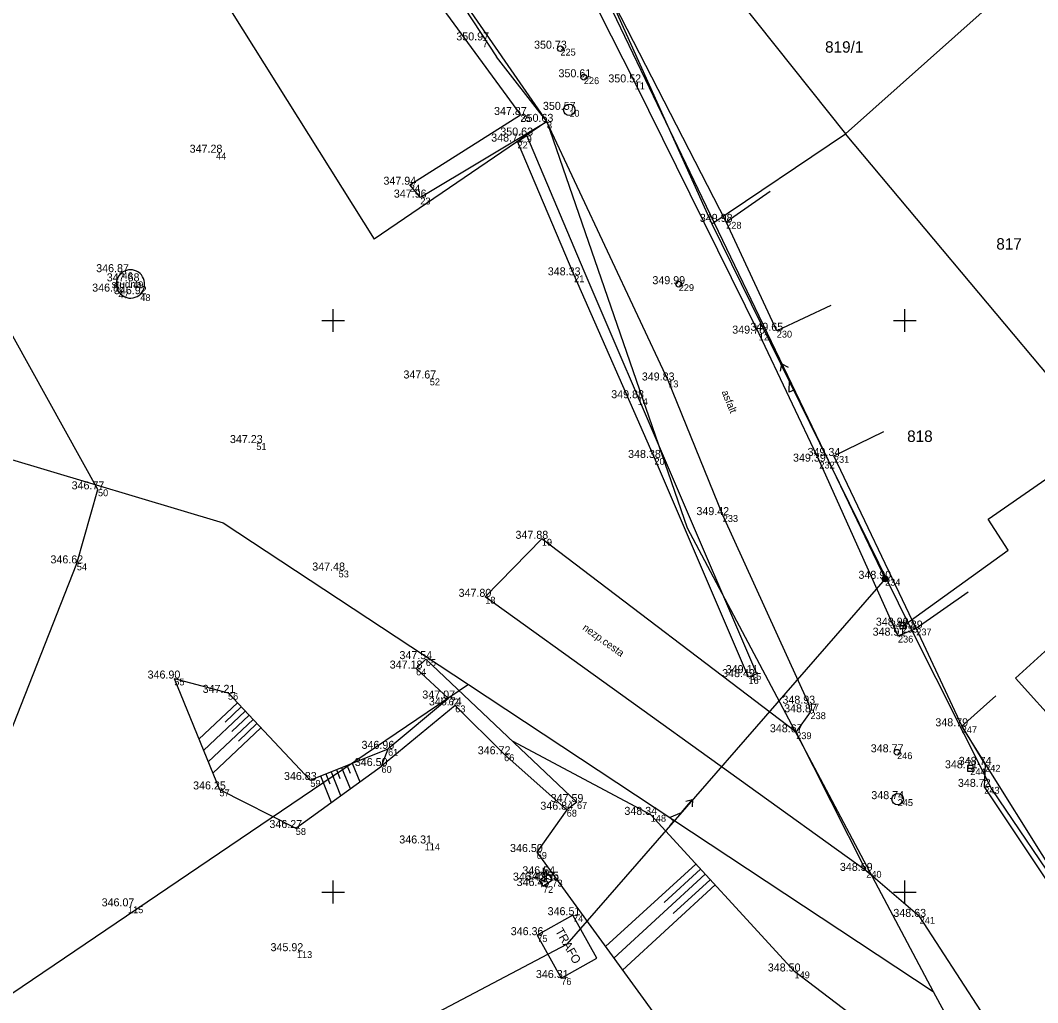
# Model space of a CAD drawing. Extents: x -614046 to -613877, y -1156755 to -1156623.
# Drawn here: x -613970.95 to -613935.35, y -1156683.87 to -1156649.5 of the extents above; entities that cross this region are included whole.
import ezdxf

# ---------------------------------------------------------------- set-up
doc = ezdxf.new("R2010")
doc.units = 0
for name, color, linetype in [('1-bod', 7, 'Continuous'), ('10-silnice', 7, 'Continuous'), ('11-zpevněné plochy', 7, 'Continuous'), ('12-nezpevněné plochy', 7, 'Continuous'), ('14-terénní hrany', 7, 'Continuous'), ('15-šrafy', 7, 'Continuous'), ('2-bod výška', 7, 'Continuous'), ('24-prisky', 7, 'Continuous'), ('25-sloupy', 7, 'Continuous'), ('27-kanalizace značky', 7, 'Continuous'), ('28-vodovod značky', 7, 'Continuous'), ('3-bod číslo', 7, 'Continuous'), ('32-elekrické vedení', 7, 'Continuous'), ('40-popisy povrchů', 7, 'Continuous'), ('41-Popis objektů', 7, 'Continuous'), ('50-hranice parcel KN', 7, 'Continuous'), ('61-hektarová síť', 7, 'Continuous'), ('7-plot', 7, 'Continuous')]:
    doc.layers.add(name, color=color, linetype=linetype)

# ---------------------------------------------------------------- blocks, each defined once
blk = doc.blocks.new('6.30')
at = {"layer": '27-kanalizace značky'}
blk.add_line((-0.249, 0.002), (0.251, 0.002), dxfattribs=at)
blk.add_lwpolyline([(-0.25, -0.248), (0.251, -0.249), (0.251, 0.251), (-0.249, 0.251)], close=True, dxfattribs=at)
blk = doc.blocks.new('6.14A_1')
at = {"layer": '28-vodovod značky'}
blk.add_circle((0, 0), 0.25, dxfattribs=at)
blk = doc.blocks.new('6.20_1')
at = {"layer": '27-kanalizace značky'}
blk.add_circle((0, 0), 0.5, dxfattribs=at)
blk = doc.blocks.new('6.01A_1')
at = {"layer": '25-sloupy'}
for radius in [0.25, 0.2, 0.15, 0.1, 0.05]:
    blk.add_circle((0, 0), radius, dxfattribs=at)
blk = doc.blocks.new('PE_1')
at = {"layer": '24-prisky'}
for p, q in [((-0.25, 1.126), (-0.25, 0.5)), ((-0.25, 0.5), (0, 0.875)), ((-0.11, 0.245), (0, 0)), ((0, 0.875), (0, 0)), ((0, 0), (0.11, 0.245))]:
    blk.add_line(p, q, dxfattribs=at)
blk = doc.blocks.new('6.60_1')
at = {"layer": '32-elekrické vedení'}
for points in [[(-3, 0), (-2.5, 0), (-2.5, 0.5), (-1.5, 0), (0, 0)], [(-0.5, 0.375), (0, 0), (-0.5, -0.375)]]:
    blk.add_lwpolyline(points, dxfattribs=at)
blk = doc.blocks.new('POINT_DISPLAY')
blk.add_line((0, 0), (0, 0))

msp = doc.modelspace()

# ---------------------------------------------------------------- linework, layer by layer
at = {"layer": '10-silnice'}
for points in [[(-613960.9, -1156628.99), (-613958.35, -1156634.24), (-613954.84, -1156641.03), (-613949.45, -1156651.67), (-613945.11, -1156660.46), (-613942.99, -1156664.94), (-613940.24, -1156671.03), (-613939.6, -1156670.78), (-613938.01, -1156674.2), (-613937.19, -1156675.55), (-613937.22, -1156676.32), (-613930.03, -1156687.11), (-613926.48, -1156692.5), (-613921.2, -1156700), (-613918.96, -1156702.74), (-613916.95, -1156704.04), (-613916.91, -1156705.25), (-613915.47, -1156707.93), (-613915.57, -1156709.01), (-613915.47, -1156709.37), (-613915.3, -1156709.66), (-613915.08, -1156709.85), (-613914.78, -1156710.02), (-613906.4, -1156710.82)], [(-613937.12, -1156718.51), (-613933.57, -1156717.58), (-613925.62, -1156715.79), (-613924.84, -1156714.33), (-613924.32, -1156712.22), (-613924.87, -1156710.22), (-613924.77, -1156707.77), (-613925.4, -1156704.88), (-613927.05, -1156701.37), (-613930.42, -1156695.41), (-613933.78, -1156689.64), (-613939.48, -1156680.87), (-613941.35, -1156679.26), (-613943.8, -1156674.41), (-613943.3, -1156673.71), (-613943.36, -1156673.41), (-613946.37, -1156666.81), (-613948.28, -1156662.1), (-613952.52, -1156653.05)]]:
    msp.add_lwpolyline(points, dxfattribs=at)
at = {"layer": '11-zpevněné plochy'}
for start, end in [(123.9608, 212.772), (212.772, 123.9608)]:
    msp.add_arc((-613967.093, -1156658.721), 0.496, start, end, dxfattribs=at)
at = {"layer": '12-nezpevněné plochy'}
for p, q in [((-613968.23, -1156665.91), (-613971.76, -1156659.56)), ((-613968.97, -1156668.5), (-613968.23, -1156665.91)), ((-613971.92, -1156675.99), (-613968.97, -1156668.5))]:
    msp.add_line(p, q, dxfattribs=at)
for points in [[(-613954.68, -1156669.67), (-613952.7, -1156667.64)], [(-613943.8, -1156674.41), (-613952.7, -1156667.64)], [(-613941.35, -1156679.26), (-613954.68, -1156669.67)]]:
    msp.add_lwpolyline(points, dxfattribs=at)
at = {"layer": '14-terénní hrany'}
for p, q in [((-613965.56, -1156672.53), (-613963.68, -1156673.03)), ((-613963.68, -1156673.03), (-613960.8, -1156676.08)), ((-613960.8, -1156676.08), (-613958.08, -1156674.99)), ((-613961.31, -1156677.76), (-613958.31, -1156675.59))]:
    msp.add_line(p, q, dxfattribs=at)
for points in [[(-613965.56, -1156672.53), (-613963.98, -1156676.41), (-613961.31, -1156677.76)], [(-613940.16, -1156716.75), (-613937.91, -1156714.4), (-613933.94, -1156711.13), (-613930, -1156706.58), (-613928.58, -1156705.01), (-613927.95, -1156702.75), (-613928.18, -1156700.53), (-613933.55, -1156692.05), (-613939.5, -1156686.1), (-613943.86, -1156682.78), (-613948.89, -1156677.3), (-613953.73, -1156674.72)], [(-613951.83, -1156677.12), (-613952.88, -1156678.6), (-613948.44, -1156684.71), (-613942.44, -1156689.03), (-613937.52, -1156693.96), (-613931.49, -1156703.13), (-613933.8, -1156705.42), (-613937.38, -1156709.49), (-613940.48, -1156713.13)]]:
    msp.add_lwpolyline(points, dxfattribs=at)
at = {"layer": '15-šrafy'}
for p, q in [((-613963.353, -1156673.377), (-613964.698, -1156674.647)), ((-613963.078, -1156673.668), (-613964.536, -1156675.045)), ((-613963.215, -1156673.522), (-613963.776, -1156674.052)), ((-613962.941, -1156673.813), (-613963.546, -1156674.385)), ((-613962.803, -1156673.958), (-613964.374, -1156675.442)), ((-613962.666, -1156674.104), (-613963.317, -1156674.719)), ((-613962.529, -1156674.249), (-613964.212, -1156675.839)), ((-613959.518, -1156675.566), (-613959.407, -1156675.845)), ((-613959.332, -1156675.492), (-613959.072, -1156676.141)), ((-613960.446, -1156675.938), (-613960.074, -1156676.866)), ((-613960.261, -1156675.864), (-613960.119, -1156676.217)), ((-613960.075, -1156675.789), (-613959.74, -1156676.625)), ((-613959.889, -1156675.715), (-613959.763, -1156676.031)), ((-613959.704, -1156675.641), (-613959.406, -1156676.383)), ((-613947.31, -1156679.02), (-613950.47, -1156681.91)), ((-613946.98, -1156679.38), (-613950.18, -1156682.32)), ((-613947.15, -1156679.2), (-613948.42, -1156680.37)), ((-613946.64, -1156679.75), (-613949.88, -1156682.73)), ((-613946.81, -1156679.57), (-613948.1, -1156680.75))]:
    msp.add_line(p, q, dxfattribs=at)
at = {"layer": '24-prisky'}
for points in [[(-613952.66, -1156679.79), (-613952.33, -1156679.57), (-613952.46, -1156679.38), (-613952.79, -1156679.6)], [(-613951.61, -1156680.81), (-613952.86, -1156681.51), (-613952.02, -1156683.01), (-613950.77, -1156682.31)]]:
    msp.add_lwpolyline(points, close=True, dxfattribs=at)
at = {"layer": '32-elekrické vedení'}
for points in [[(-613958.2, -1156632.56), (-613940.69, -1156669.04)], [(-613940.69, -1156669.04), (-613951.83, -1156681.82)], [(-614000.64, -1156707.56), (-613951.83, -1156681.82)]]:
    msp.add_lwpolyline(points, dxfattribs=at)
at = {"layer": '50-hranice parcel KN'}
for points in [[(-613963.29, -1156637.07), (-613954.29, -1156650.78)], [(-613968.13, -1156641.9), (-613958.57, -1156657.15)], [(-613951.14, -1156646.88), (-613946.75, -1156656.62)], [(-613942.07, -1156653.47), (-613936.336, -1156648.353)], [(-613945.78, -1156648.82), (-613942.07, -1156653.47)], [(-613952.53, -1156653.04), (-613954.29, -1156650.78)], [(-613952.53, -1156653.04), (-613958.57, -1156657.15)], [(-613952.53, -1156653.04), (-613947.61, -1156667.26)], [(-613946.75, -1156656.62), (-613942.07, -1156653.47)], [(-613934.62, -1156662.36), (-613942.07, -1156653.47)], [(-613946.75, -1156656.62), (-613939.89, -1156670.57)], [(-613937.08, -1156666.95), (-613933.2, -1156664.26)], [(-613971.49, -1156664.79), (-613963.85, -1156667.08)], [(-613963.85, -1156667.08), (-613955.27, -1156672.74)], [(-613936.39, -1156668.04), (-613937.08, -1156666.95)], [(-613947.61, -1156667.26), (-613939.01, -1156683.48)], [(-613936.13, -1156672.52), (-613930.87, -1156667.74)], [(-613939.89, -1156670.57), (-613936.39, -1156668.04)], [(-613939.89, -1156670.57), (-613936.96, -1156676.41)], [(-613955.27, -1156672.74), (-613974.87, -1156686.01)], [(-613955.27, -1156672.74), (-613939.01, -1156683.48)], [(-613931.34, -1156677.84), (-613936.13, -1156672.52)], [(-613936.96, -1156676.41), (-613934.33, -1156680.29)], [(-613939.01, -1156683.48), (-613927.48, -1156704.79)]]:
    msp.add_lwpolyline(points, dxfattribs=at)
at = {"layer": '61-hektarová síť'}
for points in [[(-613960, -1156660.4), (-613960, -1156660), (-613960, -1156659.6)], [(-613940, -1156660.4), (-613940, -1156660), (-613940, -1156659.6)], [(-613960.4, -1156660), (-613960, -1156660), (-613959.6, -1156660)], [(-613940.4, -1156660), (-613940, -1156660), (-613939.6, -1156660)], [(-613960, -1156680.4), (-613960, -1156680), (-613960, -1156679.6)], [(-613940, -1156680.4), (-613940, -1156680), (-613940, -1156679.6)], [(-613960.4, -1156680), (-613960, -1156680), (-613959.6, -1156680)], [(-613940.4, -1156680), (-613940, -1156680), (-613939.6, -1156680)]]:
    msp.add_lwpolyline(points, dxfattribs=at)
at = {"layer": '7-plot'}
for p, q in [((-613942.59, -1156659.48), (-613944.48, -1156660.36)), ((-613937.78, -1156669.51), (-613939.6, -1156670.78))]:
    msp.add_line(p, q, dxfattribs=at)
for points in [[(-614001.09, -1156650.98), (-613963.33, -1156637.08), (-613958.98, -1156643.72), (-613952.52, -1156653.05), (-613956.95, -1156655.7)], [(-613962.04, -1156640.7), (-613960.15, -1156643.5), (-613962.22, -1156644.74), (-613961.98, -1156645.13), (-613959.93, -1156643.89), (-613958.04, -1156646.69), (-613960.96, -1156648.64), (-613960.44, -1156649.2), (-613957.51, -1156647.25), (-613953.45, -1156652.81)], [(-613946.25, -1156656.55), (-613951.23, -1156646.84), (-613949.54, -1156645.69)], [(-613956.95, -1156655.7), (-613957.32, -1156655.25), (-613953.45, -1156652.81)], [(-613945.18, -1156672.36), (-613945.47, -1156672.48), (-613948.76, -1156664.81), (-613951.57, -1156658.42), (-613953.55, -1156653.74), (-613953.23, -1156653.53)], [(-613951.22, -1156658.27), (-613953.23, -1156653.53)], [(-613946.25, -1156656.55), (-613944.713, -1156655.472)], [(-613944.48, -1156660.36), (-613946.25, -1156656.55)], [(-613945.18, -1156672.36), (-613951.22, -1156658.27)], [(-613939.6, -1156670.78), (-613942.48, -1156664.74), (-613940.74, -1156663.88)], [(-613951.47, -1156676.85), (-613956.76, -1156671.85), (-613957.1, -1156672.18), (-613955.96, -1156673.23), (-613958.08, -1156674.99)], [(-613934.24, -1156680.21), (-613938.01, -1156674.2), (-613936.81, -1156673.13)], [(-613951.83, -1156677.12), (-613954.02, -1156675.18), (-613955.73, -1156673.47), (-613958.31, -1156675.59)], [(-613958.31, -1156675.59), (-613958.08, -1156674.99)], [(-613951.47, -1156676.85), (-613951.83, -1156677.12)]]:
    msp.add_lwpolyline(points, dxfattribs=at)

# ---------------------------------------------------------------- block references
at = {"layer": '1-bod'}
for p in [(-613954.77, -1156650.2), (-613952.05, -1156650.49), (-613951.23, -1156651.49), (-613949.45, -1156651.67), (-613953.45, -1156652.81), (-613951.74, -1156652.63), (-613952.52, -1156653.05), (-613953.23, -1156653.53), (-613953.55, -1156653.74), (-613964.1, -1156654.13), (-613957.32, -1156655.25), (-613956.95, -1156655.7), (-613946.25, -1156656.55), (-613967.37, -1156658.31), (-613951.57, -1156658.42), (-613967, -1156658.63), (-613947.91, -1156658.73), (-613967.51, -1156658.99), (-613966.75, -1156659.08), (-613945.11, -1156660.46), (-613944.48, -1156660.36), (-613956.62, -1156662.03), (-613948.28, -1156662.1), (-613949.35, -1156662.72), (-613962.69, -1156664.29), (-613948.76, -1156664.81), (-613942.99, -1156664.94), (-613942.48, -1156664.74), (-613968.23, -1156665.91), (-613946.37, -1156666.81), (-613952.7, -1156667.64), (-613968.97, -1156668.5), (-613959.81, -1156668.75), (-613940.69, -1156669.04), (-613954.68, -1156669.67), (-613940.08, -1156670.68), (-613939.6, -1156670.78), (-613940.24, -1156671.03), (-613956.76, -1156671.85), (-613957.1, -1156672.18), (-613945.38, -1156672.34), (-613965.56, -1156672.53), (-613945.47, -1156672.48), (-613963.68, -1156673.03), (-613955.96, -1156673.23), (-613955.73, -1156673.47), (-613943.36, -1156673.41), (-613943.3, -1156673.71), (-613938.01, -1156674.2), (-613943.8, -1156674.41), (-613958.08, -1156674.99), (-613954.02, -1156675.18), (-613940.27, -1156675.11), (-613958.31, -1156675.59), (-613937.19, -1156675.55), (-613937.71, -1156675.67), (-613960.8, -1156676.08), (-613937.22, -1156676.32), (-613963.98, -1156676.41), (-613951.47, -1156676.85), (-613940.25, -1156676.75), (-613951.83, -1156677.12), (-613948.89, -1156677.3), (-613961.31, -1156677.76), (-613956.8, -1156678.3), (-613952.88, -1156678.6), (-613952.46, -1156679.38), (-613941.35, -1156679.26), (-613952.79, -1156679.6), (-613952.66, -1156679.79), (-613952.33, -1156679.57), (-613967.18, -1156680.5), (-613951.61, -1156680.81), (-613939.48, -1156680.87), (-613952.86, -1156681.51), (-613961.27, -1156682.07), (-613952.02, -1156683.01), (-613943.86, -1156682.78)]:
    msp.add_blockref('POINT_DISPLAY', p, dxfattribs=at)
at = {"layer": '24-prisky', "xscale": 0.4, "yscale": 0.4000000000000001}
msp.add_blockref('PE_1', (-613952.55, -1156679.6), dxfattribs=at)
at = {"layer": '25-sloupy', "xscale": 0.4, "yscale": 0.4000000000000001}
msp.add_blockref('6.01A_1', (-613940.69, -1156669.04), dxfattribs=at)
at = {"layer": '27-kanalizace značky', "xscale": 0.4, "yscale": 0.4000000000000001}
for name, p in [('6.20_1', (-613951.74, -1156652.63)), ('6.30', (-613940.08, -1156670.68)), ('6.30', (-613937.71, -1156675.67)), ('6.20_1', (-613940.25, -1156676.75))]:
    msp.add_blockref(name, p, dxfattribs=at)
at = {"layer": '28-vodovod značky', "xscale": 0.4, "yscale": 0.4000000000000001}
for p in [(-613952.05, -1156650.49), (-613951.23, -1156651.49), (-613947.91, -1156658.73), (-613940.27, -1156675.11)]:
    msp.add_blockref('6.14A_1', p, dxfattribs=at)
at = {"layer": '32-elekrické vedení', "xscale": 0.4}
for p, yscale, rotation in [((-613944.298, -1156661.523), 0.4000000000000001, 115.6404952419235), ((-613947.423, -1156676.764), 0.39999999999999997, 48.92216804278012)]:
    msp.add_blockref('6.60_1', p, dxfattribs=dict(at, yscale=yscale, rotation=rotation))

# ---------------------------------------------------------------- texts
at = {"layer": '2-bod výška'}
for s, p in [('350.97 ', (-613955.692, -1156650.2)), ('350.73 ', (-613952.972, -1156650.49)), ('350.61 ', (-613952.117, -1156651.49)), ('350.52 ', (-613950.372, -1156651.67)), ('350.57 ', (-613952.662, -1156652.63)), ('347.87 ', (-613954.372, -1156652.81)), ('350.63 ', (-613953.442, -1156653.05)), ('348.72 ', (-613954.472, -1156653.74)), ('350.63 ', (-613954.152, -1156653.53)), ('347.28 ', (-613965.022, -1156654.13)), ('347.94 ', (-613958.242, -1156655.25)), ('347.96 ', (-613957.878, -1156655.7)), ('349.98 ', (-613947.172, -1156656.55)), ('346.87 ', (-613968.292, -1156658.31)), ('348.33 ', (-613952.492, -1156658.42)), ('347.68 ', (-613967.922, -1156658.63)), ('349.99 ', (-613948.832, -1156658.73)), ('346.88 ', (-613968.432, -1156658.99)), ('346.92 ', (-613967.672, -1156659.08)), ('349.76 ', (-613946.038, -1156660.46)), ('349.65 ', (-613945.402, -1156660.36)), ('347.67 ', (-613957.542, -1156662.03)), ('349.83 ', (-613949.202, -1156662.1)), ('349.88 ', (-613950.272, -1156662.72)), ('347.23 ', (-613963.612, -1156664.29)), ('348.38 ', (-613949.682, -1156664.81)), ('349.34 ', (-613943.402, -1156664.74)), ('349.39 ', (-613943.912, -1156664.94)), ('346.77 ', (-613969.152, -1156665.91)), ('349.42 ', (-613947.292, -1156666.81)), ('347.88 ', (-613953.622, -1156667.64)), ('346.62 ', (-613969.892, -1156668.5)), ('347.48 ', (-613960.732, -1156668.75)), ('348.90 ', (-613941.623, -1156669.04)), ('347.80 ', (-613955.613, -1156669.67)), ('348.90 ', (-613941.013, -1156670.68)), ('348.89 ', (-613940.522, -1156670.78)), ('348.91 ', (-613941.127, -1156671.03)), ('347.54 ', (-613957.682, -1156671.85)), ('347.18 ', (-613958.022, -1156672.18)), ('349.11 ', (-613946.267, -1156672.34)), ('346.90 ', (-613966.493, -1156672.53)), ('348.49 ', (-613946.392, -1156672.48)), ('347.21 ', (-613964.567, -1156673.03)), ('347.07 ', (-613956.882, -1156673.23)), ('348.93 ', (-613944.282, -1156673.41)), ('346.74 ', (-613956.652, -1156673.47)), ('348.87 ', (-613944.222, -1156673.71)), ('348.67 ', (-613944.722, -1156674.41)), ('348.79 ', (-613938.932, -1156674.2)), ('346.96 ', (-613959.008, -1156674.99)), ('346.72 ', (-613954.942, -1156675.18)), ('348.77 ', (-613941.192, -1156675.11)), ('348.74 ', (-613938.112, -1156675.55)), ('346.50 ', (-613959.243, -1156675.59)), ('348.71 ', (-613938.597, -1156675.67)), ('346.83 ', (-613961.722, -1156676.08)), ('346.25 ', (-613964.902, -1156676.41)), ('348.72 ', (-613938.142, -1156676.32)), ('347.59 ', (-613952.392, -1156676.85)), ('348.74 ', (-613941.172, -1156676.75)), ('346.84 ', (-613952.752, -1156677.12)), ('348.34 ', (-613949.812, -1156677.3)), ('346.27 ', (-613962.232, -1156677.76)), ('346.31 ', (-613957.687, -1156678.3)), ('346.50 ', (-613953.813, -1156678.6)), ('346.54 ', (-613953.382, -1156679.38)), ('348.59 ', (-613942.272, -1156679.26)), ('346.43 ', (-613953.712, -1156679.6)), ('346.45 ', (-613953.582, -1156679.79)), ('346.55 ', (-613953.252, -1156679.57)), ('346.07 ', (-613968.102, -1156680.5)), ('346.51 ', (-613952.497, -1156680.81)), ('348.63 ', (-613940.402, -1156680.87)), ('346.36 ', (-613953.788, -1156681.51)), ('345.92 ', (-613962.192, -1156682.07)), ('346.31 ', (-613952.907, -1156683.01)), ('348.50 ', (-613944.793, -1156682.78))]:
    msp.add_text(s, height=0.28, dxfattribs=at).set_placement(p)
at = {"layer": '3-bod číslo'}
for s, p in [('7', (-613954.77, -1156650.44)), ('225', (-613952.05, -1156650.73)), ('226', (-613951.23, -1156651.73)), ('11', (-613949.45, -1156651.91)), ('25', (-613953.45, -1156653.05)), ('10', (-613951.74, -1156652.87)), ('8', (-613952.52, -1156653.29)), ('9', (-613953.23, -1156653.77)), ('22', (-613953.55, -1156653.98)), ('44', (-613964.1, -1156654.37)), ('24', (-613957.32, -1156655.49)), ('23', (-613956.95, -1156655.94)), ('228', (-613946.25, -1156656.79)), ('46', (-613967.37, -1156658.55)), ('21', (-613951.57, -1156658.66)), ('49', (-613967, -1156658.87)), ('229', (-613947.91, -1156658.97)), ('47', (-613967.51, -1156659.23)), ('48', (-613966.75, -1156659.32)), ('12', (-613945.11, -1156660.7)), ('230', (-613944.48, -1156660.6)), ('52', (-613956.62, -1156662.27)), ('13', (-613948.28, -1156662.34)), ('14', (-613949.35, -1156662.96)), ('51', (-613962.69, -1156664.53)), ('20', (-613948.76, -1156665.05)), ('232', (-613942.99, -1156665.18)), ('231', (-613942.48, -1156664.98)), ('50', (-613968.23, -1156666.15)), ('233', (-613946.37, -1156667.05)), ('19', (-613952.7, -1156667.88)), ('54', (-613968.97, -1156668.74)), ('53', (-613959.81, -1156668.99)), ('234', (-613940.69, -1156669.28)), ('18', (-613954.68, -1156669.91)), ('235', (-613940.08, -1156670.92)), ('237', (-613939.6, -1156671.02)), ('236', (-613940.24, -1156671.27)), ('65', (-613956.76, -1156672.09)), ('64', (-613957.1, -1156672.42)), ('15', (-613945.38, -1156672.58)), ('55', (-613965.56, -1156672.77)), ('16', (-613945.47, -1156672.72)), ('56', (-613963.68, -1156673.27)), ('62', (-613955.96, -1156673.47)), ('63', (-613955.73, -1156673.71)), ('17', (-613943.36, -1156673.65)), ('238', (-613943.3, -1156673.95)), ('247', (-613938.01, -1156674.44)), ('239', (-613943.8, -1156674.65)), ('61', (-613958.08, -1156675.23)), ('66', (-613954.02, -1156675.42)), ('246', (-613940.27, -1156675.35)), ('60', (-613958.31, -1156675.83)), ('242', (-613937.19, -1156675.79)), ('244', (-613937.71, -1156675.91)), ('59', (-613960.8, -1156676.32)), ('243', (-613937.22, -1156676.56)), ('57', (-613963.98, -1156676.65)), ('67', (-613951.47, -1156677.09)), ('245', (-613940.25, -1156676.99)), ('68', (-613951.83, -1156677.36)), ('148', (-613948.89, -1156677.54)), ('58', (-613961.31, -1156678)), ('114', (-613956.8, -1156678.54)), ('69', (-613952.88, -1156678.84)), ('70', (-613952.46, -1156679.62)), ('240', (-613941.35, -1156679.5)), ('71', (-613952.79, -1156679.84)), ('72', (-613952.66, -1156680.03)), ('73', (-613952.33, -1156679.81)), ('115', (-613967.18, -1156680.74)), ('74', (-613951.61, -1156681.05)), ('241', (-613939.48, -1156681.11)), ('75', (-613952.86, -1156681.75)), ('113', (-613961.27, -1156682.31)), ('76', (-613952.02, -1156683.25)), ('149', (-613943.86, -1156683.02))]:
    msp.add_text(s, height=0.24, dxfattribs=at).set_placement(p)
at = {"layer": '40-popisy povrchů'}
msp.add_text('studna', height=0.26, dxfattribs=at).set_placement((-613967.752, -1156658.861))
for s, rotation, p in [('asfalt', 292.0735, (-613946.417, -1156662.499)), ('nezp.cesta', 324.2676, (-613951.3, -1156670.8))]:
    msp.add_text(s, height=0.26, rotation=rotation, dxfattribs=at).set_placement(p)
at = {"layer": '41-Popis objektů'}
msp.add_text('TRAFO', height=0.3, rotation=299.2488, dxfattribs=at).set_placement((-613952.24, -1156681.36))
at = {"layer": '50-hranice parcel KN'}
for s, p in [('819/1', (-613942.79, -1156650.63)), ('817', (-613936.8, -1156657.52)), ('818', (-613939.919, -1156664.25))]:
    msp.add_text(s, height=0.4, dxfattribs=at).set_placement(p)

doc.saveas('drawing.dxf')
